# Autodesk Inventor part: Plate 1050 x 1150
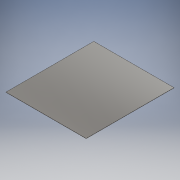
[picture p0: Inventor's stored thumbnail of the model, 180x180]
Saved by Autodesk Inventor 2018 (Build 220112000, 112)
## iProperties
Created: 2020-10
Part Number: Plate 1050 x 1150
Material: Steel, Mild
Document SubType Name: Modeling
Designer: cadcr
Density: 7.85 g/cm^3
Appearance: Semi-Polished
Author: cadcr
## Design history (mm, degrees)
sketch "Sketch1"
  geometry: L1 (-525, -575)-(525, -575); L2 (525, -575)-(525, 575); L3 (525, 575)-(-525, 575); L4 (-525, 575)-(-525, -575); L5 (-525, -575)-(525, 575); L6 (525, -575)-(-525, 575); 1 further point
  constraints: 12 end point, 2 midpoint, 2 parallel, 1 horizontal, 1 perpendicular
  dimensions: "d0" = 1050 distance of L2.end L3.end; "d1" = 1150 distance of L1.end L2.end
extrude "Extrusion1" new body sketch "Sketch1" distance "d2" = 3; taper "d3" = 0 deg
body "Solid1"
